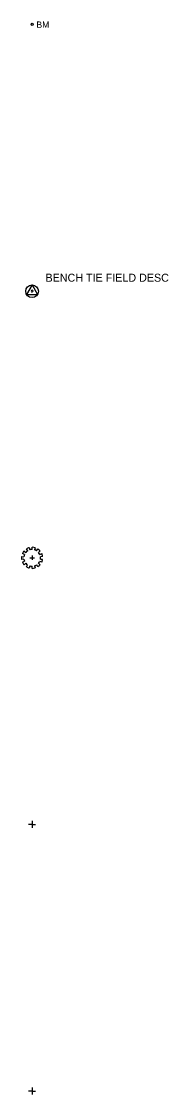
# Model space of a CAD drawing. Extents: x 98 to 2902, y -6 to 903.
# Drawn here: x 98 to 125.5, y 449.4 to 650.5 of the extents above; entities that cross this region are included whole.
import ezdxf

# ---------------------------------------------------------------- set-up
doc = ezdxf.new("R2010")
doc.units = 0
for name, color, linetype in [('V-CTRL-BMRK', 7, 'Continuous'), ('V-CTRL-VERT', 7, 'Continuous'), ('V-SITE-OTLN', 7, 'Continuous'), ('V-SITE-VEGE', 7, 'Continuous'), ('V-SURV-DATA', 7, 'Continuous')]:
    doc.layers.add(name, color=color, linetype=linetype)

msp = doc.modelspace()

# ---------------------------------------------------------------- linework, layer by layer
at = {"layer": 'V-CTRL-BMRK'}
msp.add_circle((100, 650), 0.197, dxfattribs=at)
at = {"layer": 'V-SITE-OTLN'}
for p, q in [((100, 500), (99.35, 500)), ((100, 500.65), (100, 499.35)), ((100, 500), (100.65, 500)), ((100, 450), (99.35, 450)), ((100, 450.65), (100, 449.35)), ((100, 450), (100.65, 450))]:
    msp.add_line(p, q, dxfattribs=at)
at = {"layer": 'V-SITE-VEGE'}
for p, q in [((98.49, 551.26), (98.81, 550.98)), ((99.17, 551.3), (98.93, 551.65)), ((99.46, 551.89), (99.56, 551.47)), ((100, 551.53), (100.01, 551.96)), ((100.57, 551.88), (100.45, 551.47)), ((100.84, 551.29), (101.08, 551.64)), ((101.51, 551.27), (101.19, 550.99)), ((98.03, 550.25), (98.46, 550.18)), ((98.46, 549.76), (98.04, 549.69)), ((98.58, 550.61), (98.19, 550.78)), ((98.19, 549.16), (98.58, 549.35)), ((99.58, 550), (100.42, 550)), ((100, 550.42), (100, 549.58)), ((101.81, 549.15), (101.41, 549.31)), ((101.42, 550.62), (101.8, 550.82)), ((101.97, 550.25), (101.54, 550.19)), ((101.54, 549.75), (101.97, 549.7)), ((98.83, 548.96), (98.5, 548.68)), ((98.94, 548.3), (99.15, 548.68)), ((99.58, 548.48), (99.46, 548.07)), ((100, 547.99), (100, 548.42)), ((100.43, 548.49), (100.56, 548.08)), ((101.08, 548.31), (100.85, 548.68)), ((101.17, 548.95), (101.5, 548.68))]:
    msp.add_line(p, q, dxfattribs=at)
for radius, start, end in [(1.98, 139.7777, 156.0738), (1.56, 122.254, 140.086), (1.98, 105.972, 122.5562), (1.56, 89.9461, 106.3473), (1.98, 73.2952, 89.5718), (1.56, 57.451, 73.0843), (1.98, 40.7122, 57.1166), (1.98, 172.27, 188.583), (1.56, 156.0557, 172.7558), (1.56, 188.0619, 204.0332), (1.56, 318.6432, 334.5795), (1.56, 24.4529, 40.4774), (1.56, 351.5431, 7.6203), (1.98, 7.9671, 24.8625), (1.98, 335.3123, 351.7042), (1.98, 204.5394, 220.9852), (1.56, 221.2062, 236.7795), (1.98, 237.6108, 254.1981), (1.56, 254.31, 270.043), (1.98, 270.0356, 286.342), (1.56, 285.9559, 303.0564), (1.98, 302.8434, 319.0222)]:
    msp.add_arc((100, 549.98), radius, start, end, dxfattribs=at)
at = {"layer": 'V-SURV-DATA'}
for p, q in [((100, 601.14), (98.97, 599.35)), ((100, 601.14), (101.03, 599.35)), ((98.97, 599.35), (101.03, 599.35))]:
    msp.add_line(p, q, dxfattribs=at)
msp.add_circle((100, 599.95), 1.19, dxfattribs=at)
msp.add_arc((100, 600), 0.165, 92.2877, 90.5674, dxfattribs=at)

# ---------------------------------------------------------------- texts
at = {"layer": 'V-CTRL-BMRK'}
msp.add_text('BM', height=1.191, dxfattribs=at).set_placement((100.81, 649.35))
at = {"layer": 'V-CTRL-VERT'}
msp.add_text('BENCH TIE FIELD DESC', height=1.5, dxfattribs=at).set_placement((102.5, 601.75))

doc.saveas('drawing.dxf')
